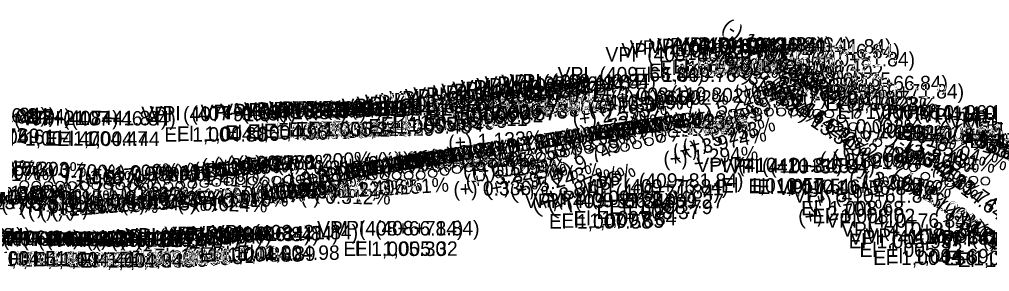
# Model space of a CAD drawing. Extents: x 16972137 to 16976737, y 12558490 to 12559551.
# Drawn here: x 16975097.7 to 16975501.5, y 12558925.9 to 12559030.6 of the extents above; entities that cross this region are included whole.
import ezdxf

# ---------------------------------------------------------------- set-up
doc = ezdxf.new("R2010")
doc.units = 0
doc.layers.add('RD_DDB_GradeTX', color=7, linetype='Continuous')
doc.layers.add('RD_DDB_PI', color=7, linetype='Continuous')

msp = doc.modelspace()

# ---------------------------------------------------------------- linework, layer by layer
at = {"layer": 'RD_DDB_PI'}
for centre in [(16975399.74, 12558991.93), (16975404.74, 12558992.17), (16975409.74, 12558992.19), (16975414.74, 12558992.16), (16975419.74, 12558992.16), (16975424.74, 12558991.88), (16975379.74, 12558988.12), (16975384.74, 12558989.77), (16975389.74, 12558990.95), (16975394.74, 12558991.6), (16975429.74, 12558991.62), (16975434.74, 12558991.42), (16975439.74, 12558989.42), (16975374.74, 12558985.68), (16975444.74, 12558986.08), (16975359.74, 12558979.85), (16975364.74, 12558981.16), (16975369.74, 12558983.25), (16975449.74, 12558982.72), (16975329.74, 12558975.94), (16975334.74, 12558976.66), (16975339.74, 12558976.94), (16975344.74, 12558977.21), (16975349.74, 12558977.54), (16975354.74, 12558978.53), (16975454.74, 12558979.44), (16975459.74, 12558976.17), (16975304.74, 12558972.17), (16975309.74, 12558972.94), (16975314.74, 12558973.7), (16975319.74, 12558974.45), (16975324.74, 12558975.2), (16975464.74, 12558972.74), (16975274.74, 12558967.5), (16975279.74, 12558968.29), (16975284.74, 12558969.08), (16975289.74, 12558969.86), (16975294.74, 12558970.63), (16975299.74, 12558971.41), (16975469.74, 12558969.07), (16975189.74, 12558963.63), (16975194.74, 12558963.55), (16975199.74, 12558963.47), (16975204.74, 12558963.78), (16975209.74, 12558964.13), (16975214.74, 12558964.23), (16975219.74, 12558964.55), (16975224.74, 12558964.83), (16975229.74, 12558965.11), (16975234.74, 12558965.36), (16975239.74, 12558965.51), (16975244.74, 12558965.61), (16975249.74, 12558965.68), (16975254.74, 12558965.75), (16975259.74, 12558965.82), (16975264.74, 12558965.9), (16975269.74, 12558966.7), (16975474.74, 12558965.41), (16975489.74, 12558964.02), (16975494.74, 12558963.79), (16975499.74, 12558963.47), (16975099.74, 12558961.88), (16975104.74, 12558961.64), (16975109.74, 12558961.56), (16975114.74, 12558961.68), (16975119.74, 12558961.53), (16975124.74, 12558961.39), (16975129.74, 12558961.5), (16975134.74, 12558961.65), (16975139.74, 12558961.51), (16975144.74, 12558961.16), (16975149.74, 12558961), (16975154.74, 12558961.08), (16975159.74, 12558961.31), (16975164.74, 12558961.66), (16975169.74, 12558962.07), (16975174.74, 12558962.48), (16975179.74, 12558962.9), (16975184.74, 12558963.33), (16975479.74, 12558962.09), (16975484.74, 12558962.76)]:
    msp.add_circle(centre, 1.75, dxfattribs=at)

# ---------------------------------------------------------------- texts
at = {"layer": 'RD_DDB_GradeTX'}
for s, rotation, p in [('(-) 13.342%', 326.2932, (16975389.68, 12559026.42)), ('(-) 8.018%', 338.1532, (16975381.13, 12559016.15)), ('(-) 13.063%', 326.8491, (16975404.49, 12559015.84)), ('(-) 13.453%', 326.0724, (16975388.24, 12559013.24)), ('(+) 6.582%', 18.2168, (16975396.62, 12558996.84)), ('(-) 13.741%', 325.5091, (16975412.28, 12559012.42)), ('(-) 13.124%', 326.7268, (16975394.42, 12559008.25)), ('(+) 4.734%', 13.3166, (16975402.77, 12558997.12)), ('(+) 9.749%', 25.9875, (16975396.34, 12558986.2)), ('(+) 2.593%', 7.3885, (16975407.67, 12558996.3)), ('(-) 14.642%', 323.7924, (16975410.07, 12559001.6)), ('(-) 0.802%', 357.7037, (16975368.67, 12558997.07)), ('(+) 5.243%', 14.6898, (16975376.84, 12558987.43)), ('(+) 9.735%', 25.955, (16975390.76, 12558983.47)), ('(+) 1.334%', 3.8169, (16975414.67, 12558995.94)), ('(-) 14.642%', 323.7924, (16975415.07, 12558997.94)), ('(+) 0.965%', 2.763, (16975418.69, 12558995.85)), ('(+) 0.065%', 0.1852, (16975423.73, 12558995.23)), ('(+) 1.334%', 3.8169, (16975334.86, 12558990.61)), ('(+) 0.965%', 2.763, (16975338.79, 12558991.99)), ('(+) 0.065%', 0.1852, (16975343.73, 12558994.98)), ('(+) 0.002%', 0.0061, (16975353.5, 12558995.15)), ('(+) 8.377%', 22.7269, (16975386.01, 12558980.31)), ('(-) 0.118%', 359.6608, (16975432.06, 12558995.06)), ('(-) 1.123%', 356.7861, (16975441.65, 12558993.94)), ('(+) 2.593%', 7.3885, (16975328.37, 12558986.02)), ('(-) 13.305%', 326.3658, (16975417.98, 12558992.36)), ('(+) 6.582%', 18.2168, (16975320.88, 12558971.91)), ('(+) 3.053%', 8.6796, (16975322.37, 12558977.9)), ('(+) 4.734%', 13.3166, (16975325.05, 12558978.72)), ('(+) 3.035%', 8.6293, (16975327.37, 12558978.65)), ('(+) 3.017%', 8.5788, (16975334.71, 12558979.74)), ('(+) 2.999%', 8.5278, (16975338.2, 12558980.25)), ('(+) 2.973%', 8.4553, (16975342.97, 12558980.94)), ('(+) 2.844%', 8.0934, (16975348.13, 12558981.59)), ('(-) 0.118%', 359.6608, (16975351.99, 12558983.53)), ('(-) 1.123%', 356.7861, (16975361.11, 12558986.44)), ('(-) 1.036%', 357.0359, (16975364.83, 12558985.97)), ('(+) 5.253%', 14.7169, (16975374.66, 12558974.46)), ('(+) 0.002%', 0.0061, (16975433.5, 12558983.16)), ('(-) 8.018%', 338.1532, (16975455.02, 12558986.52)), ('(-) 8.555%', 336.8409, (16975479.91, 12558984.55)), ('(+) 3.165%', 8.9932, (16975294.38, 12558973.65)), ('(+) 3.141%', 8.9248, (16975301.13, 12558974.69)), ('(+) 3.124%', 8.8765, (16975304.27, 12558975.16)), ('(+) 3.106%', 8.8279, (16975309.51, 12558975.96)), ('(+) 3.089%', 8.7788, (16975312.88, 12558976.47)), ('(+) 3.071%', 8.7294, (16975319.7, 12558977.51)), ('(+) 1.133%', 3.2426, (16975356.25, 12558980.88)), ('(+) 1.105%', 3.1627, (16975361.73, 12558981.16)), ('(+) 3.974%', 11.2377, (16975370.36, 12558972.46)), ('(-) 1.036%', 357.0359, (16975444.72, 12558981.83)), ('(-) 0.802%', 357.7037, (16975448.13, 12558981.88)), ('(-) 13.342%', 326.2932, (16975455.39, 12558982.58)), ('(-) 8.686%', 336.5257, (16975485.61, 12558982.47)), ('(+) 2.844%', 8.0934, (16975268.97, 12558970.33)), ('(+) 1.133%', 3.2426, (16975276.39, 12558976.35)), ('(+) 3.185%', 9.0495, (16975289.25, 12558972.85)), ('(+) 9.749%', 25.9875, (16975319.68, 12558962.18)), ('(-) 13.453%', 326.0724, (16975460.46, 12558979.12)), ('(-) 5.047%', 345.8371, (16975471.76, 12558976.82)), ('(-) 8.686%', 336.5257, (16975490.61, 12558980.3)), ('(-) 9.687%', 334.1562, (16975497.12, 12558980.17)), ('(+) 3.053%', 8.6796, (16975243.34, 12558965.84)), ('(+) 3.035%', 8.6293, (16975248.33, 12558966.65)), ('(+) 3.017%', 8.5788, (16975255.66, 12558967.82)), ('(+) 2.999%', 8.5278, (16975259.14, 12558968.4)), ('(+) 2.973%', 8.4553, (16975263.9, 12558969.19)), ('(+) 5.253%', 14.7169, (16975294.4, 12558965.78)), ('(+) 1.294%', 3.7033, (16975365.93, 12558969.57)), ('(-) 2.789%', 352.0614, (16975439.96, 12558974.84)), ('(-) 2.614%', 352.5549, (16975456.32, 12558971.95)), ('(-) 2.765%', 352.1274, (16975459.83, 12558971.95)), ('(-) 3.431%', 350.2663, (16975466.36, 12558973.01)), ('(+) 0.580%', 1.6608, (16975173.56, 12558966.59)), ('(+) 0.436%', 1.248, (16975178.63, 12558967.17)), ('(+) 0.277%', 0.7939, (16975184.06, 12558967.77)), ('(+) 0.268%', 0.7682, (16975188.58, 12558967.86)), ('(+) 1.200%', 3.4347, (16975204.94, 12558967.55)), ('(+) 3.141%', 8.9248, (16975222.16, 12558962.29)), ('(+) 3.124%', 8.8765, (16975225.29, 12558962.83)), ('(+) 3.106%', 8.8279, (16975230.52, 12558963.7)), ('(+) 0.414%', 1.1859, (16975230.56, 12558967.56)), ('(+) 3.089%', 8.7788, (16975233.88, 12558964.27)), ('(+) 3.071%', 8.7294, (16975240.68, 12558965.37)), ('(+) 1.139%', 3.2587, (16975241.66, 12558968.8)), ('(+) 1.105%', 3.1629, (16975246.73, 12558969.05)), ('(+) 1.006%', 2.8782, (16975250.33, 12558969.15)), ('(+) 0.580%', 1.6608, (16975253.52, 12558968.91)), ('(+) 0.436%', 1.248, (16975258.61, 12558968.92)), ('(+) 0.277%', 0.7939, (16975264.05, 12558968.88)), ('(+) 0.268%', 0.7682, (16975268.58, 12558968.94)), ('(+) 0.259%', 0.7426, (16975273.46, 12558968.99)), ('(-) 0.891%', 357.4484, (16975430.71, 12558969.65)), ('(-) 1.299%', 356.2842, (16975435.72, 12558970.63)), ('(+) 0.124%', 0.3549, (16975065.25, 12558965.9)), ('(-) 0.740%', 357.881, (16975069.25, 12558965.08)), ('(+) 0.617%', 1.766, (16975070.74, 12558962.68)), ('(-) 0.557%', 358.4036, (16975073.91, 12558966.35)), ('(-) 0.303%', 359.1328, (16975088.19, 12558965.8)), ('(-) 0.700%', 357.9941, (16975104.13, 12558965.24)), ('(-) 1.566%', 355.5233, (16975110.68, 12558964.11)), ('(-) 1.877%', 354.6387, (16975116.17, 12558963.35)), ('(+) 1.719%', 4.9123, (16975122.43, 12558960.99)), ('(+) 1.200%', 3.4347, (16975125.09, 12558962.76)), ('(-) 0.598%', 358.2878, (16975133.82, 12558964.11)), ('(+) 1.406%', 4.0225, (16975145.57, 12558962.63)), ('(-) 0.557%', 358.4036, (16975153.87, 12558964.12)), ('(+) 1.251%', 3.5806, (16975156.63, 12558963.6)), ('(+) 1.139%', 3.2587, (16975161.8, 12558964.25)), ('(+) 1.105%', 3.1629, (16975166.86, 12558964.64)), ('(+) 1.006%', 2.8782, (16975170.44, 12558965.13)), ('(+) 3.222%', 9.152, (16975203.11, 12558959.01)), ('(+) 3.185%', 9.0495, (16975210.31, 12558960.28)), ('(-) 0.313%', 359.1029, (16975209.84, 12558966.32)), ('(+) 3.165%', 8.9932, (16975215.42, 12558961.15)), ('(+) 1.105%', 3.1627, (16975282.52, 12558964.76)), ('(+) 3.222%', 9.152, (16975283.94, 12558959.88)), ('(+) 1.294%', 3.7033, (16975286.11, 12558964.4)), ('(+) 3.974%', 11.2377, (16975291.99, 12558956.89)), ('(+) 5.243%', 14.6898, (16975302.66, 12558955.58)), ('(+) 8.377%', 22.7269, (16975312.61, 12558949.56)), ('(+) 9.735%', 25.955, (16975319.33, 12558948.7)), ('(-) 13.741%', 325.5091, (16975477.34, 12558967.72)), ('(-) 1.411%', 355.9634, (16975163.97, 12558962.81)), ('(+) 5.018%', 14.0851, (16975426.48, 12558951.24)), ('(-) 3.065%', 351.2879, (16975442.84, 12558963.15)), ('(-) 2.846%', 351.9003, (16975448.13, 12558961.68)), ('(-) 13.124%', 326.7268, (16975460.49, 12558964.9)), ('(-) 13.063%', 326.8491, (16975464.09, 12558962.58)), ('(-) 14.642%', 323.7924, (16975480.75, 12558964.74)), ('(+) 0.832%', 2.3829, (16975078.56, 12558954.42)), ('(-) 1.411%', 355.9634, (16975083.33, 12558956.47)), ('(+) 0.904%', 2.589, (16975084.36, 12558954.73)), ('(-) 0.313%', 359.1029, (16975129.67, 12558955.57)), ('(-) 0.312%', 359.107, (16975134.73, 12558955.49)), ('(+) 1.409%', 4.0302, (16975181.21, 12558953.8)), ('(+) 1.639%', 4.6854, (16975186, 12558954.37)), ('(+) 1.652%', 4.7219, (16975190.83, 12558954.78)), ('(+) 0.259%', 0.7426, (16975193.62, 12558955.96)), ('(+) 1.665%', 4.758, (16975196.18, 12558955.24)), ('(+) 0.336%', 0.9625, (16975198.43, 12558955.78)), ('(+) 1.719%', 4.9123, (16975203.15, 12558955.88)), ('(+) 1.223%', 3.4983, (16975220.14, 12558955.7)), ('(+) 1.406%', 4.0225, (16975226.21, 12558956.27)), ('(+) 1.251%', 3.5806, (16975237.21, 12558956.62)), ('(+) 0.336%', 0.9625, (16975278.41, 12558957.13)), ('(+) 0.425%', 1.2186, (16975063.71, 12558951.09)), ('(+) 0.085%', 0.2447, (16975073.66, 12558953.7)), ('(-) 0.624%', 358.2125, (16975083.49, 12558954.07)), ('(+) 0.310%', 0.8881, (16975090.24, 12558951.08)), ('(-) 0.209%', 359.401, (16975093.52, 12558953.8)), ('(+) 0.911%', 2.6078, (16975097.64, 12558949.47)), ('(-) 0.115%', 359.6692, (16975101.87, 12558953.82)), ('(+) 1.652%', 4.7219, (16975111.11, 12558948.2)), ('(+) 1.665%', 4.758, (16975116.48, 12558948.6)), ('(-) 0.983%', 357.1871, (16975118.1, 12558951.97)), ('(-) 0.314%', 359.1012, (16975125.07, 12558952.32)), ('(+) 0.477%', 1.3674, (16975129.66, 12558953.03)), ('(-) 0.545%', 358.4399, (16975138.37, 12558952.02)), ('(+) 1.223%', 3.4983, (16975140.29, 12558950.82)), ('(+) 0.425%', 1.2186, (16975143.69, 12558952.79)), ('(+) 0.414%', 1.1859, (16975150.83, 12558953.91)), ('(+) 0.617%', 1.766, (16975151.07, 12558953.15)), ('(-) 0.624%', 358.2125, (16975163.45, 12558951.57)), ('(+) 0.310%', 0.8881, (16975170.23, 12558952.32)), ('(+) 0.911%', 2.6078, (16975177.55, 12558953.11)), ('(-) 0.312%', 359.107, (16975214.72, 12558954.24)), ('(+) 1.409%', 4.0302, (16975101.42, 12558948.18)), ('(+) 1.639%', 4.6854, (16975106.28, 12558947.84)), ('(+) 2.701%', 7.6924, (16975422.23, 12558945.24)), ('(-) 14.642%', 323.7924, (16975478.66, 12558951.39)), ('(-) 13.305%', 326.3658, (16975483.75, 12558948.61))]:
    msp.add_text(s, height=6, rotation=rotation, dxfattribs=at).set_placement(p)
at = {"layer": 'RD_DDB_PI'}
for s, p in [('VPI  (409+96.84)', (16975351.74, 12559015.95)), ('VPI  (410+01.84)', (16975359.69, 12559016.6)), ('VPI  (410+06.84)', (16975363.16, 12559016.93)), ('VPI  (410+11.84)', (16975371.35, 12559017.17)), ('VPI  (410+16.84)', (16975374.81, 12559017.19)), ('VPI  (410+26.84)', (16975382.92, 12559017.16)), ('VPI  (410+41.84)', (16975399.81, 12559016.42)), ('VPI  (409+86.84)', (16975341.62, 12559013.12)), ('VPI  (409+91.84)', (16975348.27, 12559014.77)), ('VPI  (410+46.84)', (16975403.27, 12559014.42)), ('El  1,010.33', (16975364.02, 12559007.45)), ('El  1,010.46', (16975369.82, 12559008.1)), ('El  1,010.52', (16975374.26, 12559008.43)), ('El  1,010.57', (16975379.76, 12559008.67)), ('El  1,010.58', (16975384.5, 12559008.69)), ('El  1,010.57', (16975394.76, 12559008.66)), ('VPI  (410+51.84)', (16975409.57, 12559011.08)), ('El  1,010.42', (16975409.5, 12559007.92)), ('VPI  (409+66.84)', (16975321.74, 12559004.85)), ('El  1,009.76', (16975353.46, 12559004.62)), ('El  1,010.09', (16975359.7, 12559006.27)), ('El  1,010.02', (16975414.38, 12559005.92)), ('VPI  (409+26.84)', (16975281.39, 12558999.45)), ('VPI  (409+31.84)', (16975287.86, 12559000.2)), ('VPI  (409+36.84)', (16975291.33, 12559000.94)), ('VPI  (409+41.84)', (16975298.27, 12559001.66)), ('VPI  (409+46.84)', (16975301.74, 12559001.94)), ('El  1,009.35', (16975417.66, 12559002.58)), ('VPI  (410+66.84)', (16975423.27, 12559001.17)), ('VPI  (409+01.84)', (16975258.16, 12558995.63)), ('VPI  (409+06.84)', (16975261.62, 12558996.41)), ('VPI  (409+11.84)', (16975269.81, 12558997.17)), ('VPI  (409+16.84)', (16975273.27, 12558997.94)), ('VPI  (409+21.84)', (16975277.92, 12558998.7)), ('El  1,008.11', (16975336.24, 12558996.35)), ('VPI  (410+71.84)', (16975429.99, 12558997.74)), ('VPI  (408+76.84)', (16975231.8, 12558991.7)), ('VPI  (408+81.84)', (16975238.04, 12558992.5)), ('VPI  (408+86.84)', (16975241.5, 12558993.29)), ('VPI  (408+91.84)', (16975248.16, 12558994.08)), ('VPI  (408+96.84)', (16975251.62, 12558994.86)), ('El  1,007.18', (16975299.91, 12558991.7)), ('El  1,007.33', (16975302.66, 12558992.44)), ('El  1,007.47', (16975308.64, 12558993.16)), ('El  1,007.53', (16975312.84, 12558993.44)), ('El  1,007.37', (16975433.23, 12558992.67)), ('VPI  (406+91.84)', (16975048.27, 12558987.92)), ('VPI  (406+96.84)', (16975051.74, 12558987.74)), ('VPI  (407+01.84)', (16975058.33, 12558987.35)), ('VPI  (407+91.84)', (16975148.45, 12558988.33)), ('VPI  (407+96.84)', (16975151.92, 12558988.63)), ('VPI  (408+16.84)', (16975173.16, 12558989.13)), ('VPI  (408+26.84)', (16975181.27, 12558989.55)), ('VPI  (408+31.84)', (16975187.74, 12558989.83)), ('VPI  (408+36.84)', (16975191.21, 12558990.11)), ('VPI  (408+41.84)', (16975198.16, 12558990.36)), ('VPI  (408+46.84)', (16975201.62, 12558990.51)), ('VPI  (408+51.84)', (16975207.92, 12558990.61)), ('VPI  (408+56.84)', (16975211.39, 12558990.68)), ('VPI  (408+61.84)', (16975218.16, 12558990.75)), ('El  1,006.26', (16975267.93, 12558987.13)), ('El  1,006.42', (16975272.96, 12558987.91)), ('El  1,006.57', (16975278.23, 12558988.67)), ('El  1,006.73', (16975283.08, 12558989.44)), ('El  1,006.88', (16975288.08, 12558990.2)), ('El  1,007.03', (16975292.96, 12558990.95)), ('El  1,006.68', (16975438.2, 12558989.24)), ('VPI  (410+96.84)', (16975453.27, 12558989.02)), ('VPI  (411+01.84)', (16975461.35, 12558988.79)), ('VPI  (411+06.84)', (16975464.81, 12558988.47)), ('VPI  (411+11.84)', (16975473, 12558987.77)), ('VPI  (407+21.84)', (16975078.1, 12558986.68)), ('VPI  (407+41.84)', (16975098.45, 12558986.65)), ('VPI  (407+46.84)', (16975101.92, 12558986.51)), ('El  1,005.48', (16975242.96, 12558983.2)), ('El  1,005.64', (16975248.05, 12558984)), ('El  1,005.80', (16975252.81, 12558984.79)), ('El  1,005.95', (16975257.84, 12558985.58)), ('El  1,006.11', (16975266.36, 12558986.36)), ('VPI  (411+26.84)', (16975484.57, 12558985.64)), ('VPI  (411+31.84)', (16975491.05, 12558984.95)), ('VPI  (411+36.84)', (16975494.51, 12558984.09)), ('El  1,004.72', (16975058.14, 12558979.42)), ('El  1,004.69', (16975063.28, 12558979.24)), ('El  1,004.80', (16975158.05, 12558979.83)), ('El  1,004.86', (16975163.17, 12558980.13)), ('El  1,004.96', (16975183.28, 12558980.63)), ('El  1,005.05', (16975192.72, 12558981.05)), ('El  1,005.10', (16975199.47, 12558981.33)), ('El  1,005.16', (16975204.58, 12558981.61)), ('El  1,005.21', (16975209.23, 12558981.86)), ('El  1,005.24', (16975212.69, 12558982.01)), ('El  1,005.26', (16975217.69, 12558982.11)), ('El  1,005.27', (16975222.87, 12558982.18)), ('El  1,005.29', (16975227.69, 12558982.25)), ('El  1,004.94', (16975463.28, 12558980.52)), ('El  1,004.90', (16975468.17, 12558980.29)), ('El  1,004.83', (16975472.78, 12558979.97)), ('El  1,004.69', (16975478.28, 12558979.27)), ('El  1,004.61', (16975069.82, 12558978.85)), ('El  1,004.47', (16975088.46, 12558978.18)), ('El  1,004.47', (16975108.46, 12558978.15)), ('El  1,004.44', (16975113.28, 12558978.01)), ('El  1,004.27', (16975493.11, 12558977.14)), ('El  1,004.13', (16975499.44, 12558976.45)), ('VPI  (410+21.84)', (16975379.46, 12558967.16)), ('VPI  (410+31.84)', (16975389.4, 12558966.88)), ('VPI  (410+36.84)', (16975392.86, 12558966.62)), ('VPI  (409+81.84)', (16975338.16, 12558960.68)), ('VPI  (409+71.84)', (16975328.45, 12558956.16)), ('VPI  (409+76.84)', (16975331.92, 12558958.25)), ('El  1,010.57', (16975389.76, 12558958.66)), ('El  1,010.51', (16975401.12, 12558958.38)), ('El  1,010.46', (16975404.82, 12558958.12)), ('VPI  (410+56.84)', (16975413.04, 12558957.72)), ('VPI  (409+51.84)', (16975308.04, 12558952.21)), ('VPI  (409+56.84)', (16975311.5, 12558952.54)), ('VPI  (409+61.84)', (16975318.27, 12558953.53)), ('El  1,009.27', (16975348.11, 12558952.18)), ('VPI  (410+61.84)', (16975419.81, 12558954.44)), ('El  1,008.37', (16975337.93, 12558947.66)), ('El  1,008.79', (16975343.34, 12558949.75)), ('El  1,008.68', (16975423.08, 12558949.22)), ('El  1,007.58', (16975318.14, 12558943.71)), ('El  1,007.65', (16975323.26, 12558944.04)), ('El  1,007.84', (16975328.34, 12558945.03)), ('El  1,008.02', (16975427.72, 12558945.94)), ('VPI  (410+76.84)', (16975433.45, 12558944.07)), ('VPI  (408+11.84)', (16975169.69, 12558938.78)), ('VPI  (408+21.84)', (16975177.8, 12558939.23)), ('VPI  (408+66.84)', (16975221.62, 12558940.82)), ('VPI  (408+71.84)', (16975228.33, 12558940.9)), ('VPI  (410+81.84)', (16975439.69, 12558940.41)), ('VPI  (406+81.84)', (16975038.16, 12558938)), ('VPI  (406+86.84)', (16975041.62, 12558937.95)), ('VPI  (407+06.84)', (16975061.8, 12558936.88)), ('VPI  (407+11.84)', (16975069.99, 12558936.64)), ('VPI  (407+16.84)', (16975073.45, 12558936.56)), ('VPI  (407+26.84)', (16975081.56, 12558936.53)), ('VPI  (407+31.84)', (16975088.04, 12558936.39)), ('VPI  (407+36.84)', (16975091.5, 12558936.5)), ('VPI  (407+51.84)', (16975108.22, 12558936.16)), ('VPI  (407+56.84)', (16975111.68, 12558936)), ('VPI  (407+61.84)', (16975118.45, 12558936.08)), ('VPI  (407+66.84)', (16975121.92, 12558936.31)), ('VPI  (407+71.84)', (16975128.63, 12558936.66)), ('VPI  (407+76.84)', (16975132.09, 12558937.07)), ('VPI  (407+81.84)', (16975138.33, 12558937.48)), ('VPI  (407+86.84)', (16975141.8, 12558937.9)), ('VPI  (408+01.84)', (16975158.04, 12558938.55)), ('VPI  (408+06.84)', (16975161.5, 12558938.47)), ('VPI  (410+86.84)', (16975443.16, 12558937.09)), ('El  1,005.95', (16975442.84, 12558935.57)), ('VPI  (410+91.84)', (16975449.81, 12558937.76)), ('VPI  (411+16.84)', (16975476.46, 12558937.01)), ('VPI  (411+21.84)', (16975481.11, 12558936.3)), ('El  1,004.98', (16975188.2, 12558930.73)), ('El  1,005.30', (16975232.52, 12558932.32)), ('El  1,005.32', (16975237.31, 12558932.4)), ('El  1,005.22', (16975447.37, 12558931.91)), ('El  1,004.51', (16975074.58, 12558928.38)), ('El  1,004.46', (16975078.28, 12558928.14)), ('El  1,004.45', (16975083.08, 12558928.06)), ('El  1,004.44', (16975093.28, 12558928.03)), ('El  1,004.42', (16975097.96, 12558927.89)), ('El  1,004.44', (16975103.28, 12558928)), ('El  1,004.37', (16975118.05, 12558927.66)), ('El  1,004.34', (16975122.87, 12558927.5)), ('El  1,004.35', (16975127.66, 12558927.58)), ('El  1,004.40', (16975133.17, 12558927.81)), ('El  1,004.47', (16975138.46, 12558928.16)), ('El  1,004.55', (16975142.84, 12558928.57)), ('El  1,004.63', (16975147.9, 12558928.98)), ('El  1,004.72', (16975153.14, 12558929.4)), ('El  1,004.85', (16975167.96, 12558930.05)), ('El  1,004.83', (16975172.78, 12558929.97)), ('El  1,004.89', (16975178.17, 12558930.28)), ('El  1,004.56', (16975453.05, 12558928.59)), ('El  1,004.69', (16975458.28, 12558929.26)), ('El  1,004.54', (16975483.05, 12558928.51)), ('El  1,004.40', (16975488.17, 12558927.8))]:
    msp.add_text(s, height=6, dxfattribs=at).set_placement(p)

doc.saveas('drawing.dxf')
